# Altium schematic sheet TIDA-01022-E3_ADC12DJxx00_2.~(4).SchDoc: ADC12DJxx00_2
size 431 x 279 mm; Date: Not shown in title block; ApprovedBy: Not shown in title block; CheckedBy: Not shown in title block; Author: Not shown in title block; CompanyName: Not shown in title block; DrawnBy: Avinash N; Engineer: Not shown in title block; Organization: Not shown in title block; Address1: Not shown in title block; Address2: Not shown in title block; Address3: Not shown in title block; Address4: Not shown in title block; DocumentNumber: 1; Revision: Use project parameter SCH_Rev; SheetNumber: 8; SheetTotal: 26; PageSetup: Record=PageOptions¦CenterHorizontal=True¦CenterVertical=True¦PrintScale=1.00¦XCorrection=1.00¦YCorrection=1.00¦PrintKind=0¦BorderSize=5000000¦LeftOffset=0¦BottomOffset=0¦Orientation=2¦PaperLength=1000¦PaperWidth=1000¦Scale=100¦PaperSource=15¦PrintQuality=600¦MediaType=1¦DitherType=10¦PaperKind=Letter¦PrintScaleMode=1
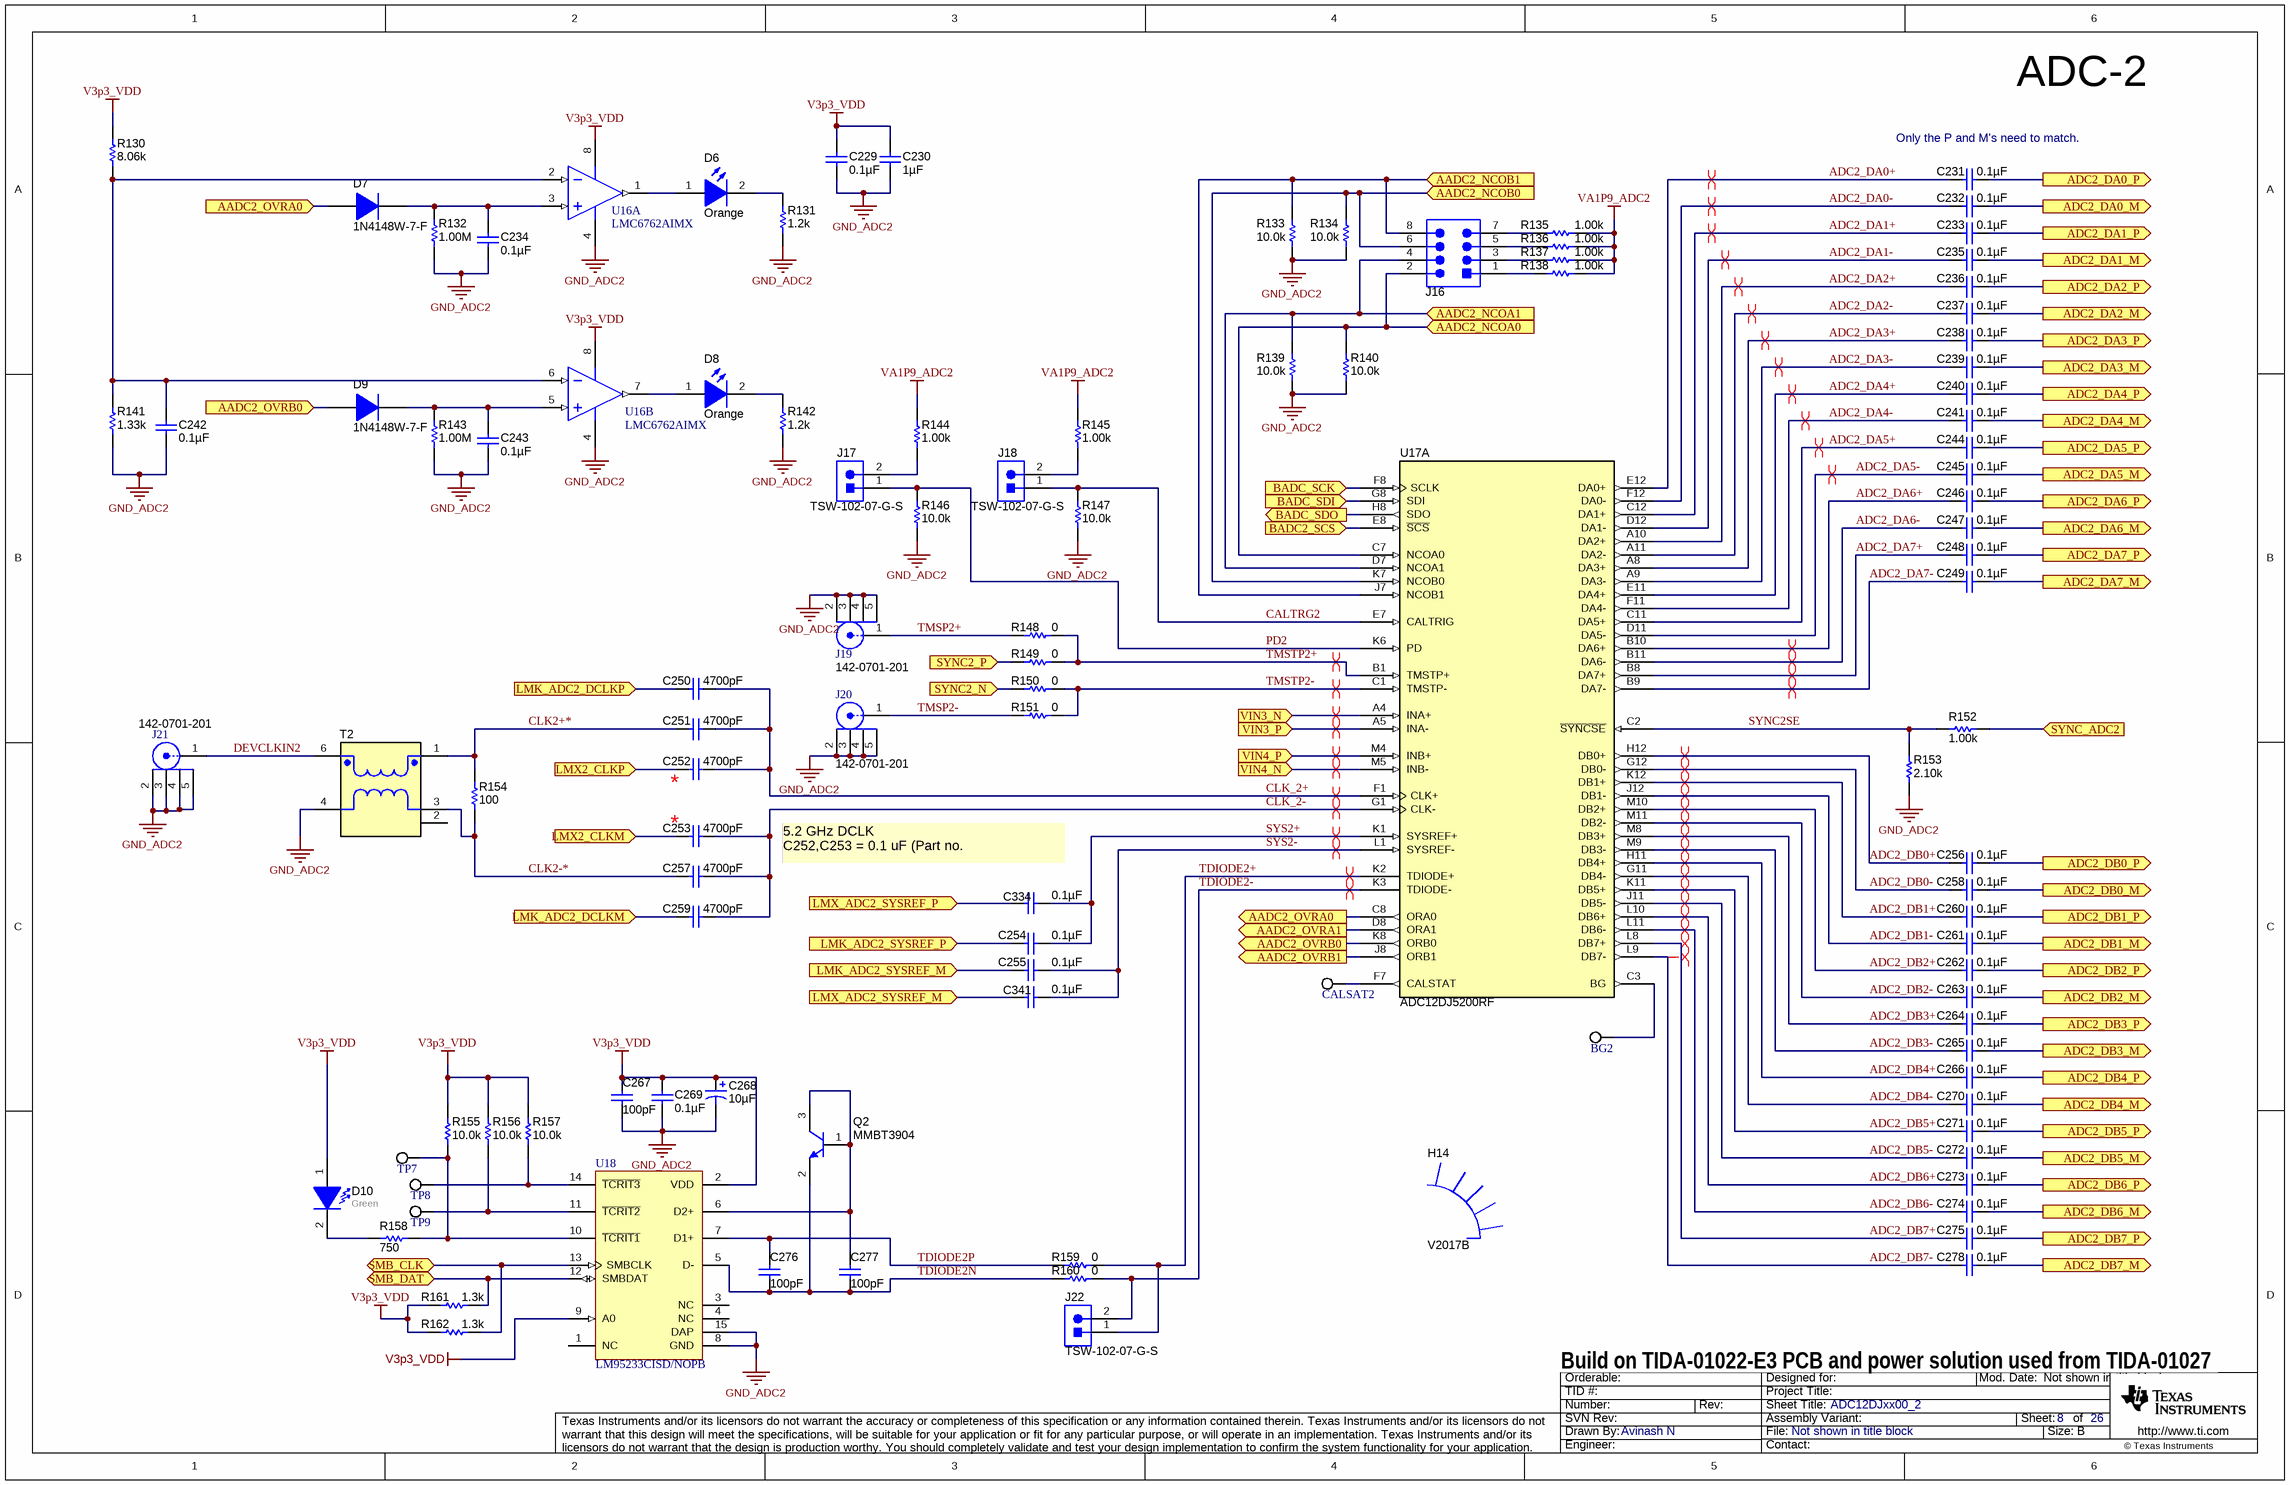
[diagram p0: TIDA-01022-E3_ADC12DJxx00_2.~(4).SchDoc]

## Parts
BG2  5002  [Keystone5002]  (value not drawn)
C229  ValueDisplayed: 0.1µF  [0402]  (hidden comment: C1005X7R1E104M050BB)
C230  ValueDisplayed: 1µF  [0603]  (hidden comment: C1608X5R1A105K080AC)
C231  ValueDisplayed: 0.1µF  [0201_adc]  (hidden comment: GRM033C71A104KE14D)
C232  ValueDisplayed: 0.1µF  [0201_adc]  (hidden comment: GRM033C71A104KE14D)
C233  ValueDisplayed: 0.1µF  [0201_adc]  (hidden comment: GRM033C71A104KE14D)
C234  ValueDisplayed: 0.1µF  [0402]  (hidden comment: C1005X7R1E104M050BB)
C235  ValueDisplayed: 0.1µF  [0201_adc]  (hidden comment: GRM033C71A104KE14D)
C236  ValueDisplayed: 0.1µF  [0201_adc]  (hidden comment: GRM033C71A104KE14D)
C237  ValueDisplayed: 0.1µF  [0201_adc]  (hidden comment: GRM033C71A104KE14D)
C238  ValueDisplayed: 0.1µF  [0201_adc]  (hidden comment: GRM033C71A104KE14D)
C239  ValueDisplayed: 0.1µF  [0201_adc]  (hidden comment: GRM033C71A104KE14D)
C240  ValueDisplayed: 0.1µF  [0201_adc]  (hidden comment: GRM033C71A104KE14D)
C241  ValueDisplayed: 0.1µF  [0201_adc]  (hidden comment: GRM033C71A104KE14D)
C242  ValueDisplayed: 0.1µF  [0402]  (hidden comment: C1005X7R1E104M050BB)
C243  ValueDisplayed: 0.1µF  [0402]  (hidden comment: C1005X7R1E104M050BB)
C244  ValueDisplayed: 0.1µF  [0201_adc]  (hidden comment: GRM033C71A104KE14D)
C245  ValueDisplayed: 0.1µF  [0201_adc]  (hidden comment: GRM033C71A104KE14D)
C246  ValueDisplayed: 0.1µF  [0201_adc]  (hidden comment: GRM033C71A104KE14D)
C247  ValueDisplayed: 0.1µF  [0201_adc]  (hidden comment: GRM033C71A104KE14D)
C248  ValueDisplayed: 0.1µF  [0201_adc]  (hidden comment: GRM033C71A104KE14D)
C249  ValueDisplayed: 0.1µF  [0201_adc]  (hidden comment: GRM033C71A104KE14D)
C250  ValueDisplayed: 4700pF  [0402]  (hidden comment: GRM155R71H472KA01D)
C251  ValueDisplayed: 4700pF  [0402]  (hidden comment: GRM155R71H472KA01D)
C252  ValueDisplayed: 4700pF  [0402]  (hidden comment: GRM155R71H472KA01D)
C253  ValueDisplayed: 4700pF  [0402]  (hidden comment: GRM155R71H472KA01D)
C254  ValueDisplayed: 0.1µF  [0402]  (hidden comment: C1005X7R1E104M050BB)
C255  ValueDisplayed: 0.1µF  [0402]  (hidden comment: C1005X7R1E104M050BB)
C256  ValueDisplayed: 0.1µF  [0201_adc]  (hidden comment: GRM033C71A104KE14D)
C257  ValueDisplayed: 4700pF  [0402]  (hidden comment: GRM155R71H472KA01D)
C258  ValueDisplayed: 0.1µF  [0201_adc]  (hidden comment: GRM033C71A104KE14D)
C259  ValueDisplayed: 4700pF  [0402]  (hidden comment: GRM155R71H472KA01D)
C260  ValueDisplayed: 0.1µF  [0201_adc]  (hidden comment: GRM033C71A104KE14D)
C261  ValueDisplayed: 0.1µF  [0201_adc]  (hidden comment: GRM033C71A104KE14D)
C262  ValueDisplayed: 0.1µF  [0201_adc]  (hidden comment: GRM033C71A104KE14D)
C263  ValueDisplayed: 0.1µF  [0201_adc]  (hidden comment: GRM033C71A104KE14D)
C264  ValueDisplayed: 0.1µF  [0201_adc]  (hidden comment: GRM033C71A104KE14D)
C265  ValueDisplayed: 0.1µF  [0201_adc]  (hidden comment: GRM033C71A104KE14D)
C266  ValueDisplayed: 0.1µF  [0201_adc]  (hidden comment: GRM033C71A104KE14D)
C267  ValueDisplayed: 100pF  [0402]  (hidden comment: GRM1555C1H101JA01D)
C268  ValueDisplayed: 10µF  [3528-21]  (hidden comment: 293D106X0010B2TE3)
C269  ValueDisplayed: 0.1µF  [0402]  (hidden comment: C1005X7R1E104M050BB)
C270  ValueDisplayed: 0.1µF  [0201_adc]  (hidden comment: GRM033C71A104KE14D)
C271  ValueDisplayed: 0.1µF  [0201_adc]  (hidden comment: GRM033C71A104KE14D)
C272  ValueDisplayed: 0.1µF  [0201_adc]  (hidden comment: GRM033C71A104KE14D)
C273  ValueDisplayed: 0.1µF  [0201_adc]  (hidden comment: GRM033C71A104KE14D)
C274  ValueDisplayed: 0.1µF  [0201_adc]  (hidden comment: GRM033C71A104KE14D)
C275  ValueDisplayed: 0.1µF  [0201_adc]  (hidden comment: GRM033C71A104KE14D)
C276  ValueDisplayed: 100pF  [0402]  (hidden comment: GRM1555C1H101JA01D)
C277  ValueDisplayed: 100pF  [0402]  (hidden comment: GRM1555C1H101JA01D)
C278  ValueDisplayed: 0.1µF  [0201_adc]  (hidden comment: GRM033C71A104KE14D)
C334  ValueDisplayed: 0.1µF  [0402]  (hidden comment: C1005X7R1E104M050BB)
C341  ValueDisplayed: 0.1µF  [0402]  (hidden comment: C1005X7R1E104M050BB)
CALSAT2  5002  [Keystone5002]  (value not drawn)
D6  value Orange  [LED_LTST-C190]  (hidden comment: LTST-C190KFKT)
D7  1N4148W-7-F  [SOD-123]
D8  value Orange  [LED_LTST-C190]  (hidden comment: LTST-C190KFKT)
D9  1N4148W-7-F  [SOD-123]
D10  value Green  [LED_LTST-C190]  (hidden comment: LTST-C190GKT)
H14  V2017B  [ASMN_V2017B]  (mechanical)
J16  TSW-104-07-G-D  [TSW-104-07-G-D]  (value not drawn)
J17  TSW-102-07-G-S  [TSW-102-07-G-S]
J18  TSW-102-07-G-S  [TSW-102-07-G-S]
J19  142-0701-201  [Johnson_142-0701-20x]
J20  142-0701-201  [Johnson_142-0701-20x]
J21  142-0701-201  [Johnson_142-0701-20x]
J22  TSW-102-07-G-S  [TSW-102-07-G-S]
Q2  MMBT3904  [SOT-23]
R130  ValueDisplayed: 8.06k  [0402]  (hidden comment: CRCW04028K06FKED)
R131  ValueDisplayed: 1.2k  [0402]  (hidden comment: CRCW04021K20JNED)
R132  ValueDisplayed: 1.00M  [0402]  (hidden comment: ERJ-2RKF1004X)
R133  ValueDisplayed: 10.0k  [0402]  (hidden comment: ERJ-2RKF1002X)
R134  ValueDisplayed: 10.0k  [0402]  (hidden comment: ERJ-2RKF1002X)
R135  ValueDisplayed: 1.00k  [0402]  (hidden comment: ERJ-2RKF1001X)
R136  ValueDisplayed: 1.00k  [0402]  (hidden comment: ERJ-2RKF1001X)
R137  ValueDisplayed: 1.00k  [0402]  (hidden comment: ERJ-2RKF1001X)
R138  ValueDisplayed: 1.00k  [0402]  (hidden comment: ERJ-2RKF1001X)
R139  ValueDisplayed: 10.0k  [0402]  (hidden comment: ERJ-2RKF1002X)
R140  ValueDisplayed: 10.0k  [0402]  (hidden comment: ERJ-2RKF1002X)
R141  ValueDisplayed: 1.33k  [0402]  (hidden comment: CRCW04021K33FKED)
R142  ValueDisplayed: 1.2k  [0402]  (hidden comment: CRCW04021K20JNED)
R143  ValueDisplayed: 1.00M  [0402]  (hidden comment: ERJ-2RKF1004X)
R144  ValueDisplayed: 1.00k  [0402]  (hidden comment: ERJ-2RKF1001X)
R145  ValueDisplayed: 1.00k  [0402]  (hidden comment: ERJ-2RKF1001X)
R146  ValueDisplayed: 10.0k  [0402]  (hidden comment: ERJ-2RKF1002X)
R147  ValueDisplayed: 10.0k  [0402]  (hidden comment: ERJ-2RKF1002X)
R148  ValueDisplayed: 0  [0402]  (hidden comment: CRCW04020000Z0ED)
R149  ValueDisplayed: 0  [0402]  (hidden comment: CRCW04020000Z0ED)
R150  ValueDisplayed: 0  [0402]  (hidden comment: CRCW04020000Z0ED)
R151  ValueDisplayed: 0  [0402]  (hidden comment: CRCW04020000Z0ED)
R152  ValueDisplayed: 1.00k  [0402]  (hidden comment: ERJ-2RKF1001X)
R153  ValueDisplayed: 2.10k  [0402]  (hidden comment: CRCW04022K10FKED)
R154  ValueDisplayed: 100  [0402]  (hidden comment: CRCW0402100RFKED)
R155  ValueDisplayed: 10.0k  [0402]  (hidden comment: ERJ-2RKF1002X)
R156  ValueDisplayed: 10.0k  [0402]  (hidden comment: ERJ-2RKF1002X)
R157  ValueDisplayed: 10.0k  [0402]  (hidden comment: ERJ-2RKF1002X)
R158  ValueDisplayed: 750  [0603]  (hidden comment: CRCW0603750RJNEA)
R159  ValueDisplayed: 0  [0402]  (hidden comment: CRCW04020000Z0ED)
R160  ValueDisplayed: 0  [0402]  (hidden comment: CRCW04020000Z0ED)
R161  ValueDisplayed: 1.3k  [0603]  (hidden comment: RC0603JR-071K3L)
R162  ValueDisplayed: 1.3k  [0603]  (hidden comment: RC0603JR-071K3L)
T2  TC1-1-43X+  [MNC_AT1521]  (value not drawn)
TP7  5002  [Keystone5002]  (value not drawn)
TP8  5002  [Keystone5002]  (value not drawn)
TP9  5002  [Keystone5002]  (value not drawn)
U16  LMC6762AIMX  [M08A_N]  (parts A,B of 2)
U17  ADC12DJ5200RF  [AAV0144A]  (part A of 2)
U18  LM95233CISD/NOPB  [SDA14B]

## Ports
AADC2_NCOA0 (in), AADC2_NCOA1 (in), AADC2_NCOB0 (in), AADC2_NCOB1 (in), AADC2_OVRA0 (in), AADC2_OVRA0 (out), AADC2_OVRA1 (out), AADC2_OVRB0 (in), AADC2_OVRB0 (out), AADC2_OVRB1 (out), ADC2_DA0_M (out), ADC2_DA0_P (out), ADC2_DA1_M (out), ADC2_DA1_P (out), ADC2_DA2_M (out), ADC2_DA2_P (out), ADC2_DA3_M (out), ADC2_DA3_P (out), ADC2_DA4_M (out), ADC2_DA4_P (out), ADC2_DA5_M (out), ADC2_DA5_P (out), ADC2_DA6_M (out), ADC2_DA6_P (out), ADC2_DA7_M (out), ADC2_DA7_P (out), ADC2_DB0_M (out), ADC2_DB0_P (out), ADC2_DB1_M (out), ADC2_DB1_P (out), ADC2_DB2_M (out), ADC2_DB2_P (out), ADC2_DB3_M (out), ADC2_DB3_P (out), ADC2_DB4_M (out), ADC2_DB4_P (out), ADC2_DB5_M (out), ADC2_DB5_P (out), ADC2_DB6_M (out), ADC2_DB6_P (out), ADC2_DB7_M (out), ADC2_DB7_P (out), BADC2_SCS (in), BADC_SCK (in), BADC_SDI (in), BADC_SDO (out), LMK_ADC2_DCLKM (in), LMK_ADC2_DCLKP (in), LMK_ADC2_SYSREF_M (in), LMK_ADC2_SYSREF_P (in), LMX2_CLKM (in), LMX2_CLKP (in), LMX_ADC2_SYSREF_M (in), LMX_ADC2_SYSREF_P (in), SMB_CLK (bidir), SMB_DAT (bidir), SYNC2_N (in), SYNC2_P (in), SYNC_ADC2 (in), VIN3_N (in), VIN3_P (in), VIN4_N (in), VIN4_P (in)

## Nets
GND_ADC2: C229.1 C230.2 C234.1 C242.1 C243.1 C267.2 C268.2(-) C269.2 J19.2 J19.3 J19.4 J19.5 J20.2 J20.3 J20.4 J20.5 J21.2 J21.3 J21.4 J21.5 R131.1 R132.1 R133.2 R134.2 R139.2 R140.2 R141.1 R142.1 R143.1 R146.1 R147.1 R153.1 T2.4 U16.4(V-) U18.8(GND) U18.15(DAP)
V3p3_VDD: C229.2 C230.1 C267.1 C268.1(+) C269.1 D10.1(A) R130.2 R155.2 R156.2 R157.2 R161.2 R162.2 U16.8(V+) U18.2(VDD) U18.9(A0)
VA1P9_ADC2: R135.1 R136.1 R137.1 R138.1 R144.2 R145.2
AADC2_NCOA0: J16.2 R140.1 U17.C7(NCOA0) ; port AADC2_NCOA0
AADC2_NCOA1: J16.4 R139.1 U17.D7(NCOA1) ; port AADC2_NCOA1
AADC2_NCOB0: J16.6 R134.1 U17.K7(NCOB0) ; port AADC2_NCOB0
AADC2_NCOB1: J16.8 R133.1 U17.J7(NCOB1) ; port AADC2_NCOB1
AADC2_OVRA0: D7.2(A) U17.C8(ORA0) ; port AADC2_OVRA0
AADC2_OVRA1: U17.D8(ORA1) ; port AADC2_OVRA1
AADC2_OVRB0: D9.2(A) U17.K8(ORB0) ; port AADC2_OVRB0
AADC2_OVRB1: U17.J8(ORB1) ; port AADC2_OVRB1
ADC2_DA0+: C231.1 U17.E12(DA0+)
ADC2_DA0-: C232.1 U17.F12(DA0-)
ADC2_DA0_M: C232.2 ; port ADC2_DA0_M
ADC2_DA0_P: C231.2 ; port ADC2_DA0_P
ADC2_DA1+: C233.1 U17.C12(DA1+)
ADC2_DA1-: C235.1 U17.D12(DA1-)
ADC2_DA1_M: C235.2 ; port ADC2_DA1_M
ADC2_DA1_P: C233.2 ; port ADC2_DA1_P
ADC2_DA2+: C236.1 U17.A10(DA2+)
ADC2_DA2-: C237.1 U17.A11(DA2-)
ADC2_DA2_M: C237.2 ; port ADC2_DA2_M
ADC2_DA2_P: C236.2 ; port ADC2_DA2_P
ADC2_DA3+: C238.1 U17.A8(DA3+)
ADC2_DA3-: C239.1 U17.A9(DA3-)
ADC2_DA3_M: C239.2 ; port ADC2_DA3_M
ADC2_DA3_P: C238.2 ; port ADC2_DA3_P
ADC2_DA4+: C240.1 U17.E11(DA4+)
ADC2_DA4-: C241.1 U17.F11(DA4-)
ADC2_DA4_M: C241.2 ; port ADC2_DA4_M
ADC2_DA4_P: C240.2 ; port ADC2_DA4_P
ADC2_DA5+: C244.1 U17.C11(DA5+)
ADC2_DA5-: C245.1 U17.D11(DA5-)
ADC2_DA5_M: C245.2 ; port ADC2_DA5_M
ADC2_DA5_P: C244.2 ; port ADC2_DA5_P
ADC2_DA6+: C246.1 U17.B10(DA6+)
ADC2_DA6-: C247.1 U17.B11(DA6-)
ADC2_DA6_M: C247.2 ; port ADC2_DA6_M
ADC2_DA6_P: C246.2 ; port ADC2_DA6_P
ADC2_DA7+: C248.1 U17.B8(DA7+)
ADC2_DA7-: C249.1 U17.B9(DA7-)
ADC2_DA7_M: C249.2 ; port ADC2_DA7_M
ADC2_DA7_P: C248.2 ; port ADC2_DA7_P
ADC2_DB0+: C256.1 U17.H12(DB0+)
ADC2_DB0-: C258.1 U17.G12(DB0-)
ADC2_DB0_M: C258.2 ; port ADC2_DB0_M
ADC2_DB0_P: C256.2 ; port ADC2_DB0_P
ADC2_DB1+: C260.1 U17.K12(DB1+)
ADC2_DB1-: C261.1 U17.J12(DB1-)
ADC2_DB1_M: C261.2 ; port ADC2_DB1_M
ADC2_DB1_P: C260.2 ; port ADC2_DB1_P
ADC2_DB2+: C262.1 U17.M10(DB2+)
ADC2_DB2-: C263.1 U17.M11(DB2-)
ADC2_DB2_M: C263.2 ; port ADC2_DB2_M
ADC2_DB2_P: C262.2 ; port ADC2_DB2_P
ADC2_DB3+: C264.1 U17.M8(DB3+)
ADC2_DB3-: C265.1 U17.M9(DB3-)
ADC2_DB3_M: C265.2 ; port ADC2_DB3_M
ADC2_DB3_P: C264.2 ; port ADC2_DB3_P
ADC2_DB4+: C266.1 U17.H11(DB4+)
ADC2_DB4-: C270.1 U17.G11(DB4-)
ADC2_DB4_M: C270.2 ; port ADC2_DB4_M
ADC2_DB4_P: C266.2 ; port ADC2_DB4_P
ADC2_DB5+: C271.1 U17.K11(DB5+)
ADC2_DB5-: C272.1 U17.J11(DB5-)
ADC2_DB5_M: C272.2 ; port ADC2_DB5_M
ADC2_DB5_P: C271.2 ; port ADC2_DB5_P
ADC2_DB6+: C273.1 U17.L10(DB6+)
ADC2_DB6-: C274.1 U17.L11(DB6-)
ADC2_DB6_M: C274.2 ; port ADC2_DB6_M
ADC2_DB6_P: C273.2 ; port ADC2_DB6_P
ADC2_DB7+: C275.1 U17.L8(DB7+)
ADC2_DB7-: C278.1 U17.L9(DB7-)
ADC2_DB7_M: C278.2 ; port ADC2_DB7_M
ADC2_DB7_P: C275.2 ; port ADC2_DB7_P
BADC2_SCS: U17.E8(~{SCS}) ; port BADC2_SCS
BADC_SCK: U17.F8(SCLK) ; port BADC_SCK
BADC_SDI: U17.G8(SDI) ; port BADC_SDI
BADC_SDO: U17.H8(SDO) ; port BADC_SDO
CALTRG2: J18.1 R147.2 U17.E7(CALTRIG)
CLK2+*: C251.2 R154.2 T2.1
CLK2-*: C257.2 R154.1 T2.3
CLK_2+: C250.1 C251.1 C252.1 U17.F1(CLK+)
CLK_2-: C253.1 C257.1 C259.1 U17.G1(CLK-)
DEVCLKIN2: J21.1 T2.6
LMK_ADC2_DCLKM: C259.2 ; port LMK_ADC2_DCLKM
LMK_ADC2_DCLKP: C250.2 ; port LMK_ADC2_DCLKP
LMK_ADC2_SYSREF_M: C255.1 ; port LMK_ADC2_SYSREF_M
LMK_ADC2_SYSREF_P: C254.1 ; port LMK_ADC2_SYSREF_P
LMX2_CLKM: C253.2 ; port LMX2_CLKM
LMX2_CLKP: C252.2 ; port LMX2_CLKP
LMX_ADC2_SYSREF_M: C341.1 ; port LMX_ADC2_SYSREF_M
LMX_ADC2_SYSREF_P: C334.1 ; port LMX_ADC2_SYSREF_P
PD2: J17.1 R146.2 U17.K6(PD)
SMB_CLK: R162.1 U18.13(SMBCLK) ; port SMB_CLK
SMB_DAT: R161.1 U18.12(SMBDAT) ; port SMB_DAT
SYNC2_N: R150.1 ; port SYNC2_N
SYNC2_P: R149.1 ; port SYNC2_P
SYNC2SE: R152.1 R153.2 U17.C2(~{SYNCSE})
SYNC_ADC2: R152.2 ; port SYNC_ADC2
SYS2+: C254.2 C334.2 U17.K1(SYSREF+)
SYS2-: C255.2 C341.2 U17.L1(SYSREF-)
TDIODE2+: J22.1 R159.2 U17.K2(TDIODE+)
TDIODE2-: J22.2 R160.2 U17.K3(TDIODE-)
TDIODE2N: C276.2 C277.2 Q2.2(E) R160.1 U18.5(D-)
TDIODE2P: C276.1 R159.1 U18.7(D1+)
TMSP2+: J19.1 R148.1
TMSP2-: J20.1 R151.1
TMSTP2+: R148.2 R149.2 U17.B1(TMSTP+)
TMSTP2-: R150.2 R151.2 U17.C1(TMSTP-)
VIN3_N: U17.A4(INA+) ; port VIN3_N
VIN3_P: U17.A5(INA-) ; port VIN3_P
VIN4_N: U17.M5(INB-) ; port VIN4_N
VIN4_P: U17.M4(INB+) ; port VIN4_P
NetBG2_1: BG2.1 U17.C3(BG)
NetC234_2: C234.2 D7.1(K) R132.2 U16.3(INA+)
NetC242_2: C242.2 R130.1 R141.2 U16.2(INA-) U16.6(INB-)
NetC243_2: C243.2 D9.1(K) R143.2 U16.5(INB+)
NetC277_1: C277.1 Q2.1(B) Q2.3(C) U18.6(D2+)
NetCALSAT2_1: CALSAT2.1 U17.F7(CALSTAT)
NetD6_1: D6.1(A) U16.1(OUTA)
NetD6_2: D6.2(K) R131.2
NetD8_1: D8.1(A) U16.7(OUTB)
NetD8_2: D8.2(K) R142.2
NetD10_2: D10.2(K) R158.2
NetJ16_1: J16.1 R138.2
NetJ16_3: J16.3 R137.2
NetJ16_5: J16.5 R136.2
NetJ16_7: J16.7 R135.2
NetJ17_2: J17.2 R144.1
NetJ18_2: J18.2 R145.1
NetR155_1: R155.1 R158.1 TP7.1 U18.10(~{TCRIT1})
NetR156_1: R156.1 TP9.1 U18.11(~{TCRIT2})
NetR157_1: R157.1 TP8.1 U18.14(~{TCRIT3})

Not connected (* = marked no-connect by the designer): T2 2; U18 1(NC) 3(NC) 4(NC)

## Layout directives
differential pair: ADC2_DA0+, ADC2_DA0-, ADC2_DA1+, ADC2_DA1-, ADC2_DA2+, ADC2_DA2-, ADC2_DA3+, ADC2_DA3-, ADC2_DA4+, ADC2_DA4-, ADC2_DA5+, ADC2_DA5-, ADC2_DA6+, ADC2_DA6-, ADC2_DA7+, ADC2_DA7-, ADC2_DB0+, ADC2_DB0-, ADC2_DB1+, ADC2_DB1-, ADC2_DB2+, ADC2_DB2-, ADC2_DB3+, ADC2_DB3-, ADC2_DB4+, ADC2_DB4-, ADC2_DB5+, ADC2_DB5-, ADC2_DB6+, ADC2_DB6-, ADC2_DB7+, ADC2_DB7-, CLK_2+, CLK_2-, SYS2+, SYS2-, TDIODE2+, TDIODE2-, TMSTP2+, TMSTP2-, VIN3_N, VIN3_P, VIN4_N, VIN4_P

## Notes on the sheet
- (near C231) Only the P and M's need to match.
- ADC-2
- (near C252) *
- (near C253) *
- (near C334) 5.2 GHz DCLK
  C252,C253 = 0.1 uF (Part no. 530Z104KT10T))
- Build on TIDA-01022-E3 PCB and power solution used from TIDA-01027

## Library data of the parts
BG2 CALSAT2 TP7-TP9 = 5002: Test Point, Miniature, White, TH; Manufacturer: Keystone; CompType: Test Point Loop; ContactFinish: Silver; Green_Lifecycle: Active; Green_REACh: Passed
C229 C234 C242 C243 C254 C255 C269 C334 C341 = C1005X7R1E104M050BB: CAP, CERM, 0.1 µF, 25 V, +/- 20%, X7R, 0402; Manufacturer: TDK; Polarized: N; TaMax_C: 125; TaMin_C: -55; Tolerance_%: 20; VDC_V: 25; Cap_F: 0.0000001; CompType: Capacitor; Value: 0.1uF; Value1: Unknown; Value2: 25V; U/M: EA; SizeArea_mm2: 0.5; SizeAreaWB_mm2: 3; SizeX_mm: 1; SizeZ_mm: 0.6; AEC Category: Q200
C230 = C1608X5R1A105K080AC: CAP, CERM, 1 µF, 10 V, +/- 10%, X5R, 0603; Manufacturer: TDK; Polarized: N; CompType: Capacitor; Value: 1uF; U/M: EA; Cap_F: 0.000001; Tolerance_%: 10; Value1: Unknown; Value2: 10V; TaMin_C: -55; TaMax_C: 85; SizeArea_mm2: 1.28; SizeAreaWB_mm2: 4.68; SizeX_mm: 1.6; SizeY_mm: 0.8; SizeZ_mm: 1; AEC Category: Q200
C231-C233 C235-C241 C244-C249 C256 C258 C260-C266 C270-C275 C278 = GRM033C71A104KE14D: CAP, CERM, 0.1 µF, 10 V, +/- 10%, X7S, 0201; Manufacturer: MuRata; Cap_Case: 0201; Polarized: N; TaMax_C: 125; TaMin_C: -55; Tolerance_%: 10; Cap_F: 0.0000001; CompType: Capacitor; Value: 0.1uF; Value1: Unknown; Value2: 10V; U/M: EA; SizeArea_mm2: 0.18; SizeAreaWB_mm2: 2.08; SizeX_mm: 0.6; SizeY_mm: 0.3; SizeZ_mm: 0.26; AEC Category: Q200
C250-C253 C257 C259 = GRM155R71H472KA01D: CAP, CERM, 4700 pF, 50 V, +/- 10%, X7R, 0402; Manufacturer: MuRata; Polarized: N; CompType: Capacitor; Value: 4700pF; U/M: EA; Cap_F: 0.0000000047; Tolerance_%: 10; Value1: Unknown; VDC_V: 50; Value2: 50V; TaMin_C: -55; TaMax_C: 125; SizeArea_mm2: 0.5; SizeAreaWB_mm2: 3; SizeX_mm: 1; SizeZ_mm: 0.6; AEC Category: Q200
C267 C276 C277 = GRM1555C1H101JA01D: CAP, CERM, 100 pF, 50 V, +/- 5%, C0G/NP0, 0402; Manufacturer: MuRata; Polarized: N; CompType: Capacitor; Value: 100pF; U/M: EA; Cap_F: 0.0000000001; Tolerance_%: 5; Value1: Unknown; VDC_V: 50; Value2: 50V; TaMin_C: -55; TaMax_C: 125; SizeArea_mm2: 0.5; SizeAreaWB_mm2: 3; SizeX_mm: 1; SizeZ_mm: 0.6; AEC Category: Q200
C268 = 293D106X0010B2TE3: CAP, TA, 10 µF, 10 V, +/- 20%, 2.5 ohm, SMD; Manufacturer: Vishay-Sprague; Polarized: Y; CompType: Capacitor; Value: 10uF; U/M: EA; Cap_F: 0.00001; Tolerance_%: 20; Value1: 2.5 ohm; VDC_V: 10; Value2: 10V; ESR_ohm: 2.5; IRMS_A: 0.18; TaMin_C: -55; TaMax_C: 125; Cap_Case: B; SizeAreaWB_mm2: 17.1; SizeArea_mm2: 9.8; SizeX_mm: 3.5; SizeY_mm: 2.8; SizeZ_mm: 2.1; AEC Category: Q200
D6 D8 = LTST-C190KFKT: LED, Orange, SMD; Manufacturer: Lite-On; Type: AlInGaP; Vf_V: 2; Value2: 2V; Io_A: 0.02; Power_TotalModule: 0.075; Value1: 0.075W; U/M: EA
D7 D9 = 1N4148W-7-F: Diode, Ultrafast, 100 V, 0.15 A, SOD-123; Manufacturer: Diodes Inc.; U/M: EA; Vf_V: 1.25; Value: 100V; Value1: 0.15A; Value2: 1.25V; Io_A: 0.15; Vr_V: 100; TJmax_C: 150; SizeAreaWB_mm2: 13.095; SizeArea_mm2: 6.545; SizeX_mm: 3.85; SizeY_mm: 1.7; SizeZ_mm: 1.35; AEC Category: Q101
D10 = LTST-C190GKT: LED, Green, SMD; Manufacturer: Lite-On; Vf_V: 2.1; Value2: 2.1V; Io_A: 0.02; Power_TotalModule: 0.1; Value1: 0.1W; U/M: EA
H14 = V2017B: Heatsink, 10X10X7 mm; Manufacturer: Assman WSW; SymbolCreator: a0412235
J16 = TSW-104-07-G-D: Header, 100mil, 4x2, Gold, TH; Manufacturer: Samtec; SymbolCreator: a0411947; Pitch_mm: 2.54; Gender: Male; Shrouded: N; Row_Count: 2; Current_A: 6.3; Voltage_V: 550; Cert_CSA: Y
J17 J18 J22 = TSW-102-07-G-S: Header, 100mil, 2x1, Gold, TH; Manufacturer: Samtec; SymbolCreator: a0412235; Pitch_mm: 2.54; Gender: Male; Shrouded: N; Row_Count: 1; Current_A: 6.3; Voltage_V: 550; Cert_CSA: Y
J19 J20 = 142-0701-201: Connector, TH, SMA; Manufacturer: Emerson Network Power; SymbolCreator: X0208326
J21 = 142-0701-201: Connector, SMA, TH; Manufacturer: Cinch Connectivity; SymbolCreator: X0208326; Green_Lifecycle: Not Set; Green_REACh: Incomplete
Q2 = MMBT3904, Fairchild Semiconductor: Transistor, NPN, 40 V, 0.2 A, SOT-23; CompType: BJT; PNP: 0; NPN: 1; Vceo_V: 40; Vcesat1_V: 0.2; Value: 40 V; Value1: 0.2 A; HfeMax: 300; TaMin_C: -55; TaMax_C: 150; SizeAreaWB_mm2: 14; SizeArea_mm2: 7.5; SizeX_mm: 2.5; SizeY_mm: 3; SizeZ_mm: 1.1; U/M: EA; AEC Category: Q101
R130 = CRCW04028K06FKED: RES, 8.06 k, 1%, 0.063 W, 0402; Manufacturer: Vishay-Dale; CompType: Resistor; Value: 8.06k; Res_ohm: 8060; Value_Code: 8k06; Tolerance_%: 1; Power_W: 0.063; Value2: 0.063W; VDC_V: 50; TempCo: 100 ppm/C; SizeArea_mm2: 0.5; SizeZ_mm: 0.6; EIA_Code: E96; U/M: EA; AEC Category: Q200
R131 R142 = CRCW04021K20JNED: RES, 1.2 k, 5%, 0.063 W, 0402; Manufacturer: Vishay-Dale; CompType: Resistor; Value: 1.2k; Res_ohm: 1200; Value_Code: 1k20; Tolerance_%: 5; Power_W: 0.063; Value2: 0.063W; VDC_V: 50; TempCo: 200 ppm/C; SizeArea_mm2: 0.5; SizeX_mm: 1; SizeZ_mm: 0.6; EIA_Code: E24; U/M: EA; AEC Category: Q200
R132 R143 = ERJ-2RKF1004X: RES, 1.00 M, 1%, 0.1 W, 0402; Manufacturer: Panasonic; CompType: Resistor; Value: 1.00Meg; Res_ohm: 1000000; Value_Code: 1M00; Tolerance_%: 1; Power_W: 0.1; Value2: 0.1W; VDC_V: 50; TempCo: 100 ppm/C; SizeArea_mm2: 0.5; SizeZ_mm: 0.6; EIA_Code: E96; U/M: EA; AEC Category: Q200
R133 R134 R139 R140 R146 R147 R155-R157 = ERJ-2RKF1002X: RES, 10.0 k, 1%, 0.1 W, 0402; Manufacturer: Panasonic; CompType: Resistor; Value: 10.0k; Res_ohm: 10000; Value_Code: 10k0; Tolerance_%: 1; Power_W: 0.1; Value2: 0.1W; VDC_V: 50; TempCo: 100 ppm/C; SizeArea_mm2: 0.5; SizeZ_mm: 0.6; EIA_Code: E96; U/M: EA; AEC Category: Q200
R135-R138 R144 R145 R152 = ERJ-2RKF1001X: RES, 1.00 k, 1%, 0.1 W, 0402; Manufacturer: Panasonic; CompType: Resistor; Value: 1.00k; Res_ohm: 1000; Value_Code: 1k00; Tolerance_%: 1; Power_W: 0.1; Value2: 0.1W; VDC_V: 50; TempCo: 100 ppm/C; SizeArea_mm2: 0.5; SizeZ_mm: 0.6; EIA_Code: E96; U/M: EA; AEC Category: Q200
R141 = CRCW04021K33FKED: RES, 1.33 k, 1%, 0.063 W, 0402; Manufacturer: Vishay-Dale; CompType: Resistor; Value: 1.33k; Res_ohm: 1330; Value_Code: 1k33; Tolerance_%: 1; Power_W: 0.063; Value2: 0.063W; VDC_V: 50; TempCo: 100 ppm/C; SizeArea_mm2: 0.5; SizeZ_mm: 0.6; EIA_Code: E96; U/M: EA; AEC Category: Q200
R148-R151 R159 R160 = CRCW04020000Z0ED: RES, 0, 5%, 0.063 W, 0402; Manufacturer: Vishay-Dale; CompType: Resistor; Value: 0; Value_Code: 0000; Tolerance_%: 5; Power_W: 0.063; Value2: 0.063W; VDC_V: 50; TempCo: 200 ppm/C; SizeArea_mm2: 0.5; SizeX_mm: 1; SizeZ_mm: 0.6; EIA_Code: E24; U/M: EA; AEC Category: Q200
R153 = CRCW04022K10FKED: RES, 2.10 k, 1%, 0.063 W, 0402; Manufacturer: Vishay-Dale; CompType: Resistor; Value: 2.10k; Res_ohm: 2100; Value_Code: 2k10; Tolerance_%: 1; Power_W: 0.063; Value2: 0.063W; VDC_V: 50; TempCo: 100 ppm/C; SizeArea_mm2: 0.5; SizeZ_mm: 0.6; EIA_Code: E96; U/M: EA; AEC Category: Q200
R154 = CRCW0402100RFKED: RES, 100, 1%, 0.063 W, 0402; Manufacturer: Vishay-Dale; CompType: Resistor; Value: 100; Value_Code: 100R; Tolerance_%: 1; Power_W: 0.063; Value2: 0.063W; VDC_V: 50; TempCo: 100 ppm/C; SizeArea_mm2: 0.5; SizeZ_mm: 0.6; EIA_Code: E96; U/M: EA; AEC Category: Q200
R158 = CRCW0603750RJNEA: RES, 750, 5%, 0.1 W, 0603; Manufacturer: Vishay-Dale; CompType: Resistor; Value: 750; Value_Code: 750R; Tolerance_%: 5; Power_W: 0.1; Value2: 0.1W; VDC_V: 75; TempCo: 200 ppm/C; SizeArea_mm2: 1.28; SizeX_mm: 1.6; SizeY_mm: 0.8; SizeZ_mm: 1; EIA_Code: E24; U/M: EA; AEC Category: Q200
R161 R162 = RC0603JR-071K3L: RES, 1.3 k, 5%, 0.1 W, 0603; Manufacturer: Yageo America; CompType: Resistor; Value: 1.3k; Res_ohm: 1300; Value_Code: 1k30; Tolerance_%: 5; Power_W: 0.1; Value2: 0.1W; VDC_V: 50; TempCo: 100 ppm/C; SizeArea_mm2: 1.28; SizeX_mm: 1.6; SizeY_mm: 0.8; SizeZ_mm: 1; EIA_Code: E24; U/M: EA; AEC Category: Q200
T2 = TC1-1-43X+: RF Transformer, 50 ohm, SMT; Manufacturer: Minicircuits; SymbolCreator: Altium
U16 = LMC6762AIMX: Dual Micro-Power Rail-to-Rail Input CMOS Comparator with Push-Pull Output, 8-pin Narrow SOIC; Manufacturer: Texas Instruments; PackageTopMarking: NSZXTT*LMC67*62AIM; PowerWise: N
U17 = ADC12DJ3200AAVR: 6.4-GSPS Single Channel or 3.2-GSPS Dual Channel 12-bit Analog-to-Digital Converter (ADC) Family, AAV0144A (FCBGA-144); Manufacturer: Texas Instruments; SymbolCreator: Altium; SizeArea_mm2: 100; SizeAreaWB_mm2: 144; SizeX_mm: 10; SizeZ_mm: 1.94; CompType: IC; U/M: EA
U18 = LM95233CISD: Dual Remote Diode and Local Temperature Sensor with SMBus Interface and TruTherm Technology, 15-pin LLP; Manufacturer: Texas Instruments; PackageTopMarking: NS*UZXYTT*95233CI; PowerWise: Y; CompType: Temp Sensor IC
